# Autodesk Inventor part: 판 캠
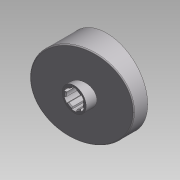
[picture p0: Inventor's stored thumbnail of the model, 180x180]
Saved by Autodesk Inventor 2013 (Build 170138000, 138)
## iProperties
Company: 한국ATC센터
Created: 2014-07
Part Number: 판 캠
Document SubType Name: 모델링
Designer: KYOUNG IL JANG
Material: 강철
Mass: 1675.75 g
Surface Area: 331.301 cm^2
Volume: 86.8262 cm^3
Density: 19.3 g/cm^3
변환 표준: STEP AP214IS
파일 이름: C:\Users\SeoGD\Desktop\?쒗뿕\??stp
전처리기: Build: 253, Release: 2010 SP1 - Date: Wed 07/29/2009
전송 단위: 밀리미터
불확실성: 0.01
Author: KYOUNG IL JANG
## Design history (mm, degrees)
node "작업 평면4"
sketch "스케치1"
  geometry: C1 r 44.5 at (0, 0); 1 further point
  constraints: 1 centre point, 1 coincident
  dimensions: "d25" = 89 diameter of C1
extrude "돌출1" new body sketch "스케치1" distance "d1" = 40; taper "d2" = 0 deg
sketch "스케치2"
  geometry: L1 (-44.5, 15)-(44.5, 38.847); L2 (-44.5, 0)-(-44.5, 40) reference; L3 (-44.5, 40)-(44.5, 40) reference; L4 (44.5, 0)-(44.5, 40) reference; 1 further point
  constraints: 2 end point, 2 point on line
  dimensions: "d26" = 15 distance of L2.start L1.start; "d27" = 75 deg angle of L1 L2
extrude "돌출2" cut sketch "스케치2" stored distance "d5" = 40; taper "d6" = 0 deg
node "작업 평면1"
sketch "스케치3"
  geometry: C1 r 13 at (0, 0); 1 further point
  constraints: 1 centre point, 1 coincident
  dimensions: "d9" = 26 diameter of C1
extrude "돌출3" join sketch "스케치3" distance "d10" = 38; taper "d11" = 0 deg
hole "구멍1" diameter "d14" = 18; stored, may be unused: countersink angle "d18" = 90 deg, drill point angle "d20" = 118 deg; dims "d12" = 10, "d13" = 10, "d15" = 6, "d16" = 4, "d17" = 2, "d19" = 8
feature "쉘2" dims "d29" = 5
sketch "스케치6"
  geometry: C1 r 17.5 at (0, 0); C2 r 14 at (0, 0) reference; 1 further point
  constraints: 1 centre point, 1 coincident
  dimensions: "d28" = 35 diameter of C1
extrude "돌출4" join sketch "스케치6" stored distance "d30" = 38; taper "d31" = 0 deg
fillet "모깎기1" dims "d32" = 3
chamfer "모따기1" distance "d21" = 1; stored, may be unused: second distance "d22" = 2, angle "d23" = 45 deg
sketch "스케치7"
  geometry: L1 (-12.374, 12.374)-(-27.931, 27.931); A1 r 39.5 centre (0, 0) between (-27.931, 27.931) and (0, 39.5) reference; 2 further points
  constraints: 2 end point, 2 point on circle, 1 point on line, 1 vertical alignment, 2 other
  dimensions: "d33" = 45 deg dimension on point (0, 0) L1.start A1.end
feature "리브1" sketch "스케치7" dims "d34" = 5, "d35" = 1, "d36" = 0
fillet "모깎기2" dims "d37" = 3
sketch "스케치8"
  geometry: L1 (2.5, 10.712)-(2.5, 8.646); L2 (-2.5, 10.712)-(-2.5, 8.646); A1 r 11 centre (0, 0) between (2.5, 10.712) and (-2.5, 10.712); A2 r 9 centre (0, 0) between (2.5, 8.646) and (-2.5, 8.646) reference; 1 further point
  constraints: 4 end point, 4 point on circle, 2 parallel, 1 centre point, 1 coincident, 1 vertical
  dimensions: "d41" = 22 diameter of A1; "d42" = 5 distance between parallel lines of L1 L2
extrude "돌출5" cut sketch "스케치8" stored distance "d43" = 38; taper "d44" = 0 deg
fillet "모깎기3" dims "d48" = 1
node "솔리드1"
node "솔리드 본체"
node "곡면 본체"
pattern_circular "원형 패턴1" dims angle "d39" = 360 deg
pattern_circular "원형 패턴2" dims angle "d46" = 360 deg
node "솔리드2"
